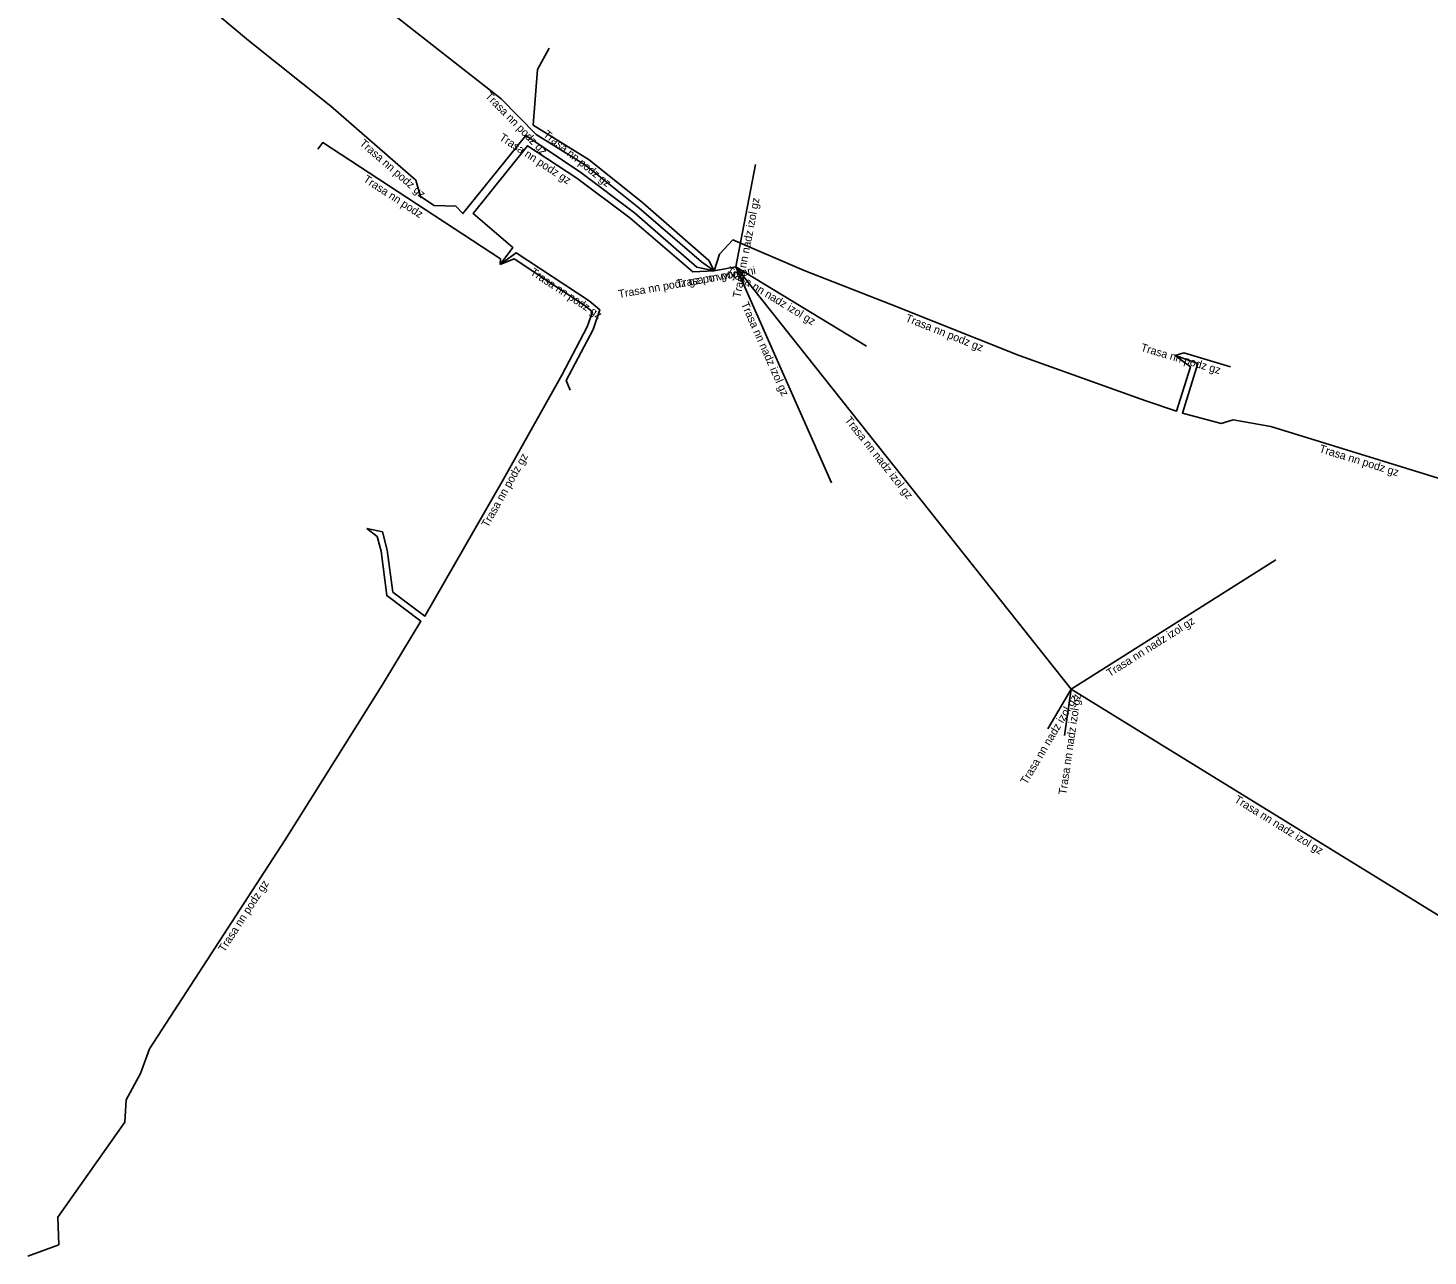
# Model space of a CAD drawing. Extents: x -484846 to -484244, y -1128177 to -1127608.
# Drawn here: x -484412.8 to -484325.4, y -1128169 to -1128092.2 of the extents above; entities that cross this region are included whole.
import ezdxf

# ---------------------------------------------------------------- set-up
doc = ezdxf.new("R2010")
doc.units = 0
doc.layers.add('Popiskový text - Ostatní atributy Trasy', color=7, linetype='Continuous')
doc.layers.add('Spojnice NN', color=7, linetype='Continuous')

msp = doc.modelspace()

# ---------------------------------------------------------------- linework, layer by layer
at = {"layer": 'Spojnice NN'}
for points in [[(-484408.15, -1128086.611), (-484407.856, -1128086.495), (-484407.348, -1128086.049), (-484399.049, -1128093.015), (-484393.9, -1128097.12), (-484388.59, -1128101.75), (-484388.3, -1128102.76), (-484387.45, -1128103.34), (-484386.09, -1128103.38), (-484385.646, -1128103.837), (-484381.711, -1128098.968), (-484378.29, -1128101.266), (-484374.927, -1128103.786), (-484371.042, -1128107.194), (-484369.96, -1128107.41)], [(-484389.376, -1128089.475), (-484389.761, -1128089.964), (-484390.436, -1128091.049), (-484383.26, -1128096.67), (-484381.08, -1128098.89), (-484377.99, -1128100.81), (-484374.67, -1128103.48), (-484370.742, -1128106.853), (-484369.96, -1128107.41)], [(-484380.264, -1128093.499), (-484380.99, -1128094.83), (-484381.265, -1128098.304), (-484377.758, -1128100.483), (-484374.413, -1128103.174), (-484370.296, -1128106.769), (-484369.96, -1128107.41)], [(-484394.723, -1128099.819), (-484394.408, -1128099.402), (-484383.303, -1128106.663), (-484383.333, -1128107.008)], [(-484383.333, -1128107.008), (-484382.541, -1128105.954), (-484385.021, -1128103.827), (-484381.62, -1128099.603), (-484378.532, -1128101.629), (-484375.232, -1128104.109), (-484371.282, -1128107.477), (-484369.96, -1128107.41)], [(-484368.6, -1128107.17), (-484367.367, -1128100.76)], [(-484369.96, -1128107.41), (-484369.62, -1128106.37), (-484368.78, -1128105.48), (-484364.33, -1128107.4), (-484358.89, -1128109.52), (-484350.91, -1128112.7), (-484343, -1128115.53), (-484341.08, -1128116.179), (-484340.201, -1128113.404), (-484341.155, -1128112.699)], [(-484378.948, -1128114.869), (-484379.192, -1128114.263), (-484377.516, -1128111.079), (-484377.097, -1128109.856), (-484377.769, -1128109.28), (-484382.316, -1128106.287), (-484383.333, -1128107.008)], [(-484391.65, -1128123.52), (-484390.671, -1128123.725), (-484390.373, -1128124.862), (-484390.033, -1128127.491), (-484388.03, -1128128.99), (-484383.12, -1128120.43), (-484379.744, -1128114.421), (-484379.467, -1128113.927), (-484377.884, -1128110.921), (-484377.563, -1128109.984), (-484378.011, -1128109.6), (-484382.459, -1128106.671), (-484383.333, -1128107.008)], [(-484368.6, -1128107.17), (-484369.96, -1128107.41)], [(-484368.6, -1128107.17), (-484369.96, -1128107.41)], [(-484347.65, -1128133.56), (-484368.6, -1128107.17)], [(-484368.6, -1128107.17), (-484360.434, -1128112.123)], [(-484368.6, -1128107.17), (-484362.63, -1128120.661)], [(-484341.155, -1128112.699), (-484340.614, -1128112.541), (-484337.704, -1128113.402)], [(-484341.155, -1128112.699), (-484339.732, -1128113.198), (-484340.7, -1128116.301), (-484338.28, -1128116.95), (-484337.54, -1128116.72), (-484335.18, -1128117.13), (-484316.906, -1128122.787), (-484316.541, -1128121.584), (-484314.64, -1128120.304), (-484315.01, -1128118.15)], [(-484412.82, -1128168.97), (-484410.902, -1128168.266), (-484410.948, -1128166.551), (-484406.774, -1128160.599), (-484406.69, -1128159.222), (-484405.8, -1128157.57), (-484405.22, -1128156.03), (-484396.76, -1128142.97), (-484390.7, -1128133.31), (-484388.27, -1128129.31), (-484390.407, -1128127.709), (-484390.767, -1128124.938), (-484391.009, -1128124.015), (-484391.65, -1128123.52)], [(-484334.863, -1128125.462), (-484347.65, -1128133.56)], [(-484347.65, -1128133.56), (-484349.115, -1128136.036)], [(-484347.65, -1128133.56), (-484348.071, -1128136.44)], [(-484347.65, -1128133.56), (-484317.94, -1128151.87)]]:
    msp.add_lwpolyline(points, dxfattribs=at)

# ---------------------------------------------------------------- texts
at = {"layer": 'Popiskový text - Ostatní atributy Trasy'}
for s, rotation, p in [('Trasa nn podz gz', 314.47914, (-484384.303, -1128096.535)), ('Trasa nn podz gz', 326.7316, (-484383.423, -1128099.197)), ('Trasa nn podz gz', 321.18387, (-484380.673, -1128098.973)), ('Trasa nn podz gz', 318.91353, (-484392.149, -1128099.509)), ('Trasa nn podz', 326.82284, (-484391.919, -1128101.806)), ('Trasa nn nadz izol gz', 79.11224, (-484368.316, -1128109.131)), ('Trasa nn podz gz', 326.64564, (-484381.488, -1128107.61)), ('Trasa nn podz gz po vytyceni', 10.00798, (-484375.895, -1128109.118)), ('Trasa nn podz', 10.00798, (-484372.266, -1128108.477)), ('Trasa nn nadz izol gz', 328.75948, (-484369.246, -1128107.539)), ('Trasa nn nadz izol gz', 293.87121, (-484368.288, -1128109.483)), ('Trasa nn podz gz', 338.2729, (-484358.051, -1128110.554)), ('Trasa nn podz gz', 343.52095, (-484343.348, -1128112.41)), ('Trasa nn nadz izol gz', 308.44497, (-484361.827, -1128116.747)), ('Trasa nn podz gz', 60.67632, (-484384.092, -1128123.488)), ('Trasa nn podz gz', 342.79928, (-484332.199, -1128118.733)), ('Trasa nn nadz izol gz', 32.34425, (-484345.247, -1128132.808)), ('Trasa nn nadz izol gz', 59.39993, (-484350.437, -1128139.55)), ('Trasa nn nadz izol gz', 81.6848, (-484347.96, -1128140.176)), ('Trasa nn nadz izol gz', 328.35472, (-484337.508, -1128140.573)), ('Trasa nn podz gz', 57.06566, (-484400.554, -1128150.023))]:
    msp.add_text(s, height=0.5, rotation=rotation, dxfattribs=at).set_placement(p)

doc.saveas('drawing.dxf')
